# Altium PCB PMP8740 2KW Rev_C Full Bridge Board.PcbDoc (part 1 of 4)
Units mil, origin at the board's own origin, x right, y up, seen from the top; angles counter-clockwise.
Board outline 10366.14 x 5900 mil, 2 copper layers (Top Layer, Bottom Layer), stack 62 mil thick; 355 components, 213 nets, 1059 pads, 574 vias.
Unrouted connection lines stored in the file: 2.
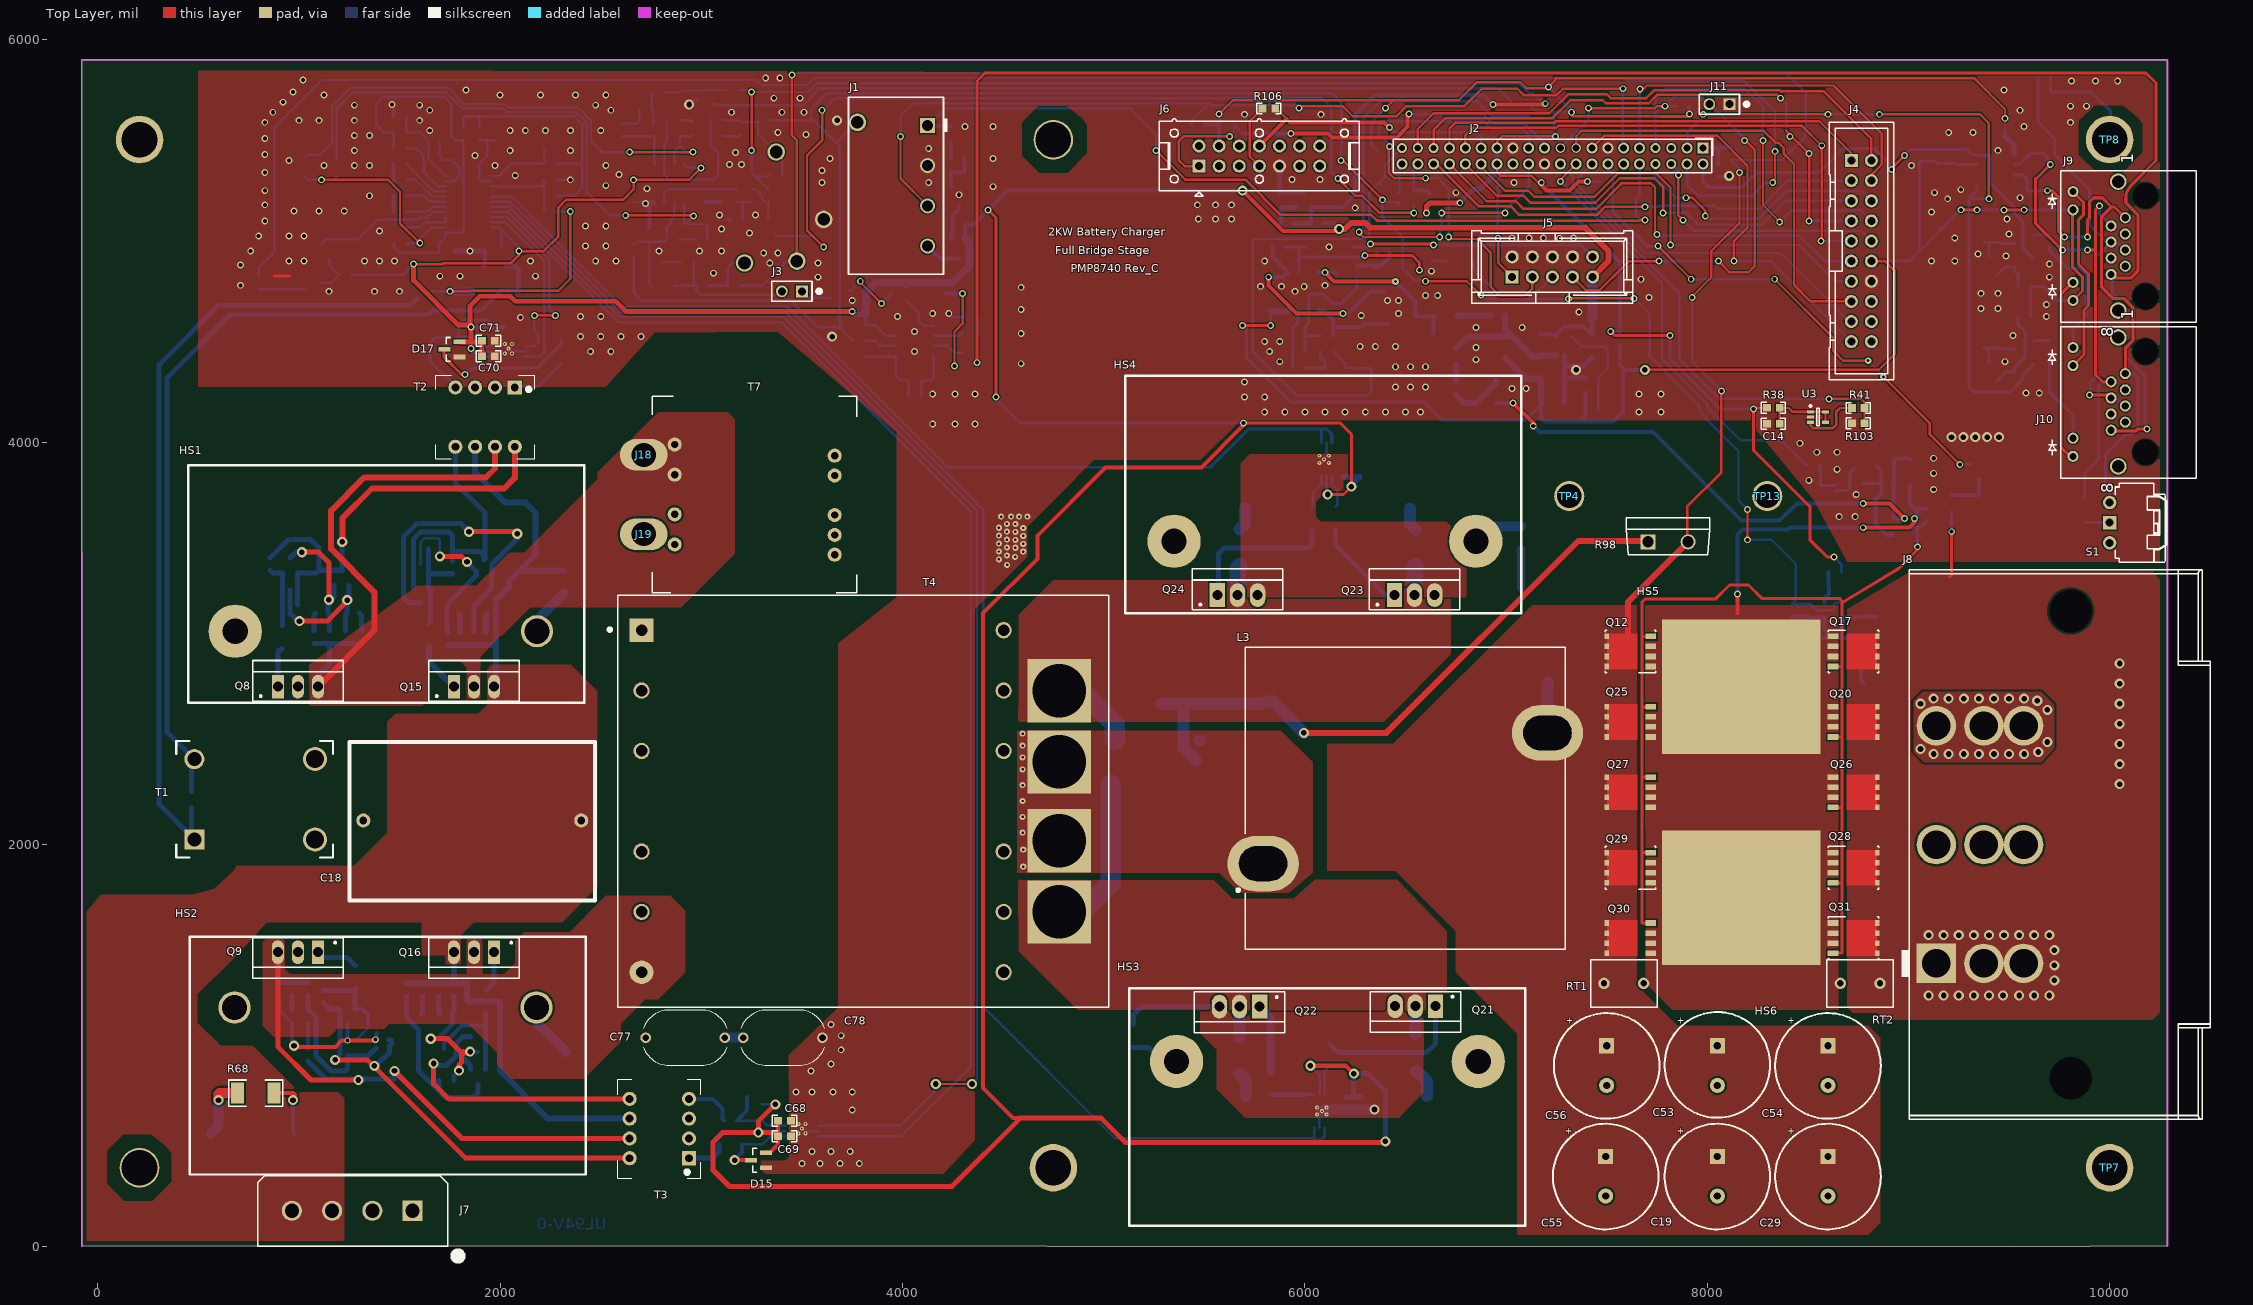
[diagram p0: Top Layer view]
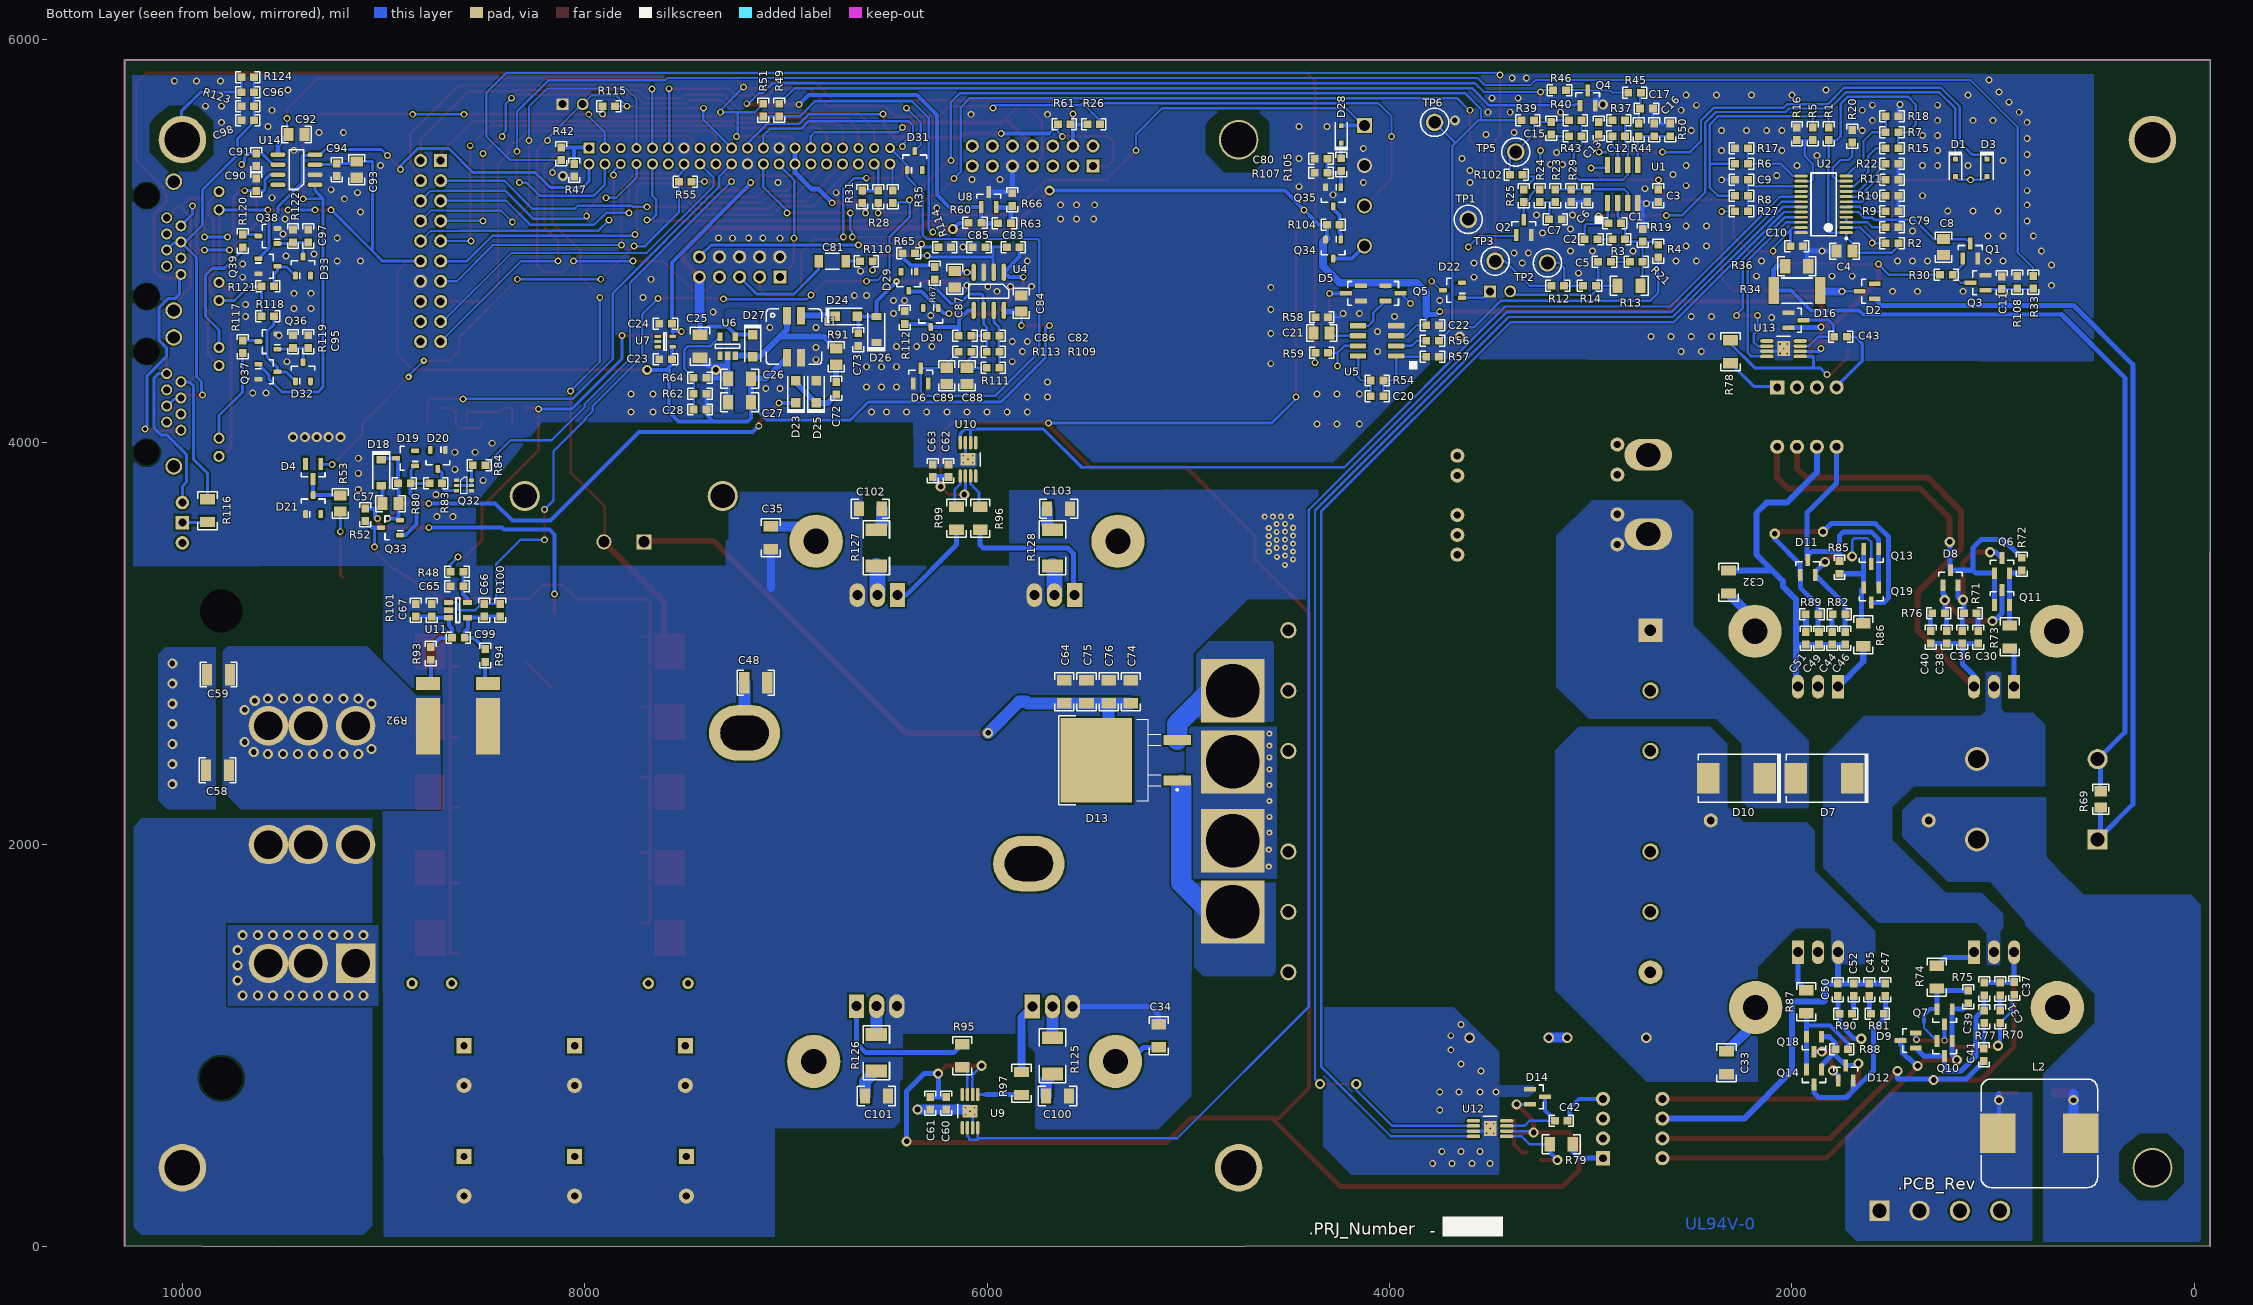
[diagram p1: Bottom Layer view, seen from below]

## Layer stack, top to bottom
Top Layer: signal copper 1.4
Dielectric: core 59.2, FR-4, Dk 4.8
Bottom Layer: signal copper 1.4

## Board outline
-78.74,5 9515,0 10287.4,5 10287.4,5900 -78.74,5900

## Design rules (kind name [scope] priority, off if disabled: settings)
AcuteAngle [All] p1: minimum=4.50000000000000E+0001 checktracksonly=FALSE
AssemblyTestPointUsage [All] p1: valid=2
Clearance [InNamedPolygon('Top Layer-gndx')] p1: gap=6
Clearance "Clearance gndx" [InNamedPolygon('Bottom Layer-gndx')] p2: gap=6
Clearance Clearance_15 [All] p3: gap=10
Clearance Clearance_18 [InNamedPolygon('Bottom Layer-No Net 17')] p4: gap=6
Clearance "Schematic Clearance Constraint_10" [InNet('NetHS2_1')] p5: gap=40
Clearance "Schematic Clearance Constraint_9" [InNet('NetHS1_2')] p6: gap=40
Clearance "Schematic Clearance Constraint_8" [InNet('NetC18_1')] p7: gap=40
Clearance "Schematic Clearance Constraint_7" [InNet('NetC30_2')] p8: gap=40
Clearance "Schematic Clearance Constraint_6" [InNet('NetC31_2')] p9: gap=40
Clearance "Schematic Clearance Constraint_5" [InNet('NetD7_1')] p10: gap=40
Clearance "Schematic Clearance Constraint_4" [InNet('NetD7_2')] p11: gap=40
Clearance "Schematic Clearance Constraint_3" [InNet('+390V')] p12: gap=40
Clearance "Schematic Clearance Constraint_2" [InNet('NetD13_1')] p13: gap=20
Clearance "Schematic Clearance Constraint_1" [InNet('NetD13_3')] p14: gap=20
Clearance "Schematic Clearance Constraint" [InNet('NetL3_1')] p15: gap=20
Clearance Clearance_14 [InNamedPolygon('Bottom Layer-No Net 9')] p16: gap=10
Clearance Clearance_13 [InNamedPolygon('Bottom Layer-No Net 9')] p17: gap=10
Clearance Clearance_12 [InNet('+390V')] p18: gap=30
Clearance Clearance_11 [InNamedPolygon('Top Layer-No Net 5')] p19: gap=30
Clearance Clearance_10 [InNamedPolygon('Top Layer-No Net 5')] p20: gap=30
Clearance Clearance_9 [InNamedPolygon('Top Layer-No Net 5')] p21: gap=20
Clearance Clearance_8 [InNamedPolygon('Top Layer-No Net 5')] p22: gap=20
Clearance Clearance_7 [InNamedPolygon('Top Layer-No Net 5')] p23: gap=20
Clearance Clearance_6 [InNamedPolygon('Bottom Layer-No Net 8')] p24: gap=10
Clearance Clearance_5 [InNamedPolygon('Top Layer-No Net 10')] p25: gap=10
Clearance Clearance_4 [InNamedPolygon('Top Layer-No Net 5')] p26: gap=10
Clearance Clearance_3 [InNamedPolygon('Bottom Layer-No Net 7')] p27: gap=10
Clearance Clearance_2 [InNamedPolygon('Bottom Layer-No Net 7')] p28: gap=10
Clearance Clearance_1 [InNamedPolygon('Top Layer-No Net 3')] p29: gap=10
Clearance Clearance_BoardEdge_MountingHoles [OnCopper and InComponentClass('Mounting Holes') vs IsKeepOut] p30: gap=40
Clearance Clearance_BoardEdge_Poly [OnCopper and InPoly vs IsKeepOut] p31: gap=40
Clearance Clearance_BoardEdge [OnCopper and Not InComponentClass('Logo') and not InComponentClass('FiducialMark') and not InRegion(1000,500,4000,800) and Not IsKeepout vs IsKeepOut] p32: gap=40
Clearance Clearance_Poly [InPolygon] p33: gap=12
ComponentClearance ComponentClearance_Logo [InComponentClass('Logo')] p1: gap=50 collisioncheckmode=3 verticalgap=100000 showdistances=FALSE
ComponentClearance ComponentClearance_ScrewToNut [(HasFootprint('NY PMS 440 0025 PH')) vs (HasFootprint('Keystone_1902C'))] p2: gap=5 collisioncheckmode=3 verticalgap=100000 showdistances=FALSE
ComponentClearance ComponentClearance_MountingHoles [InComponentClass('Mounting Holes')] p3: gap=250 collisioncheckmode=3 verticalgap=100000 showdistances=FALSE
ComponentClearance ComponentClearance_SmallPassives [HasFootprint('0201*') or HasFootprint('0402*') or HasFootprint('0508') or HasFootprint('0603*') or HasFootprint('0612') or HasFootprint('0805*') or HasFootprint('0815*') or HasFootprint('0830*') or HasFootprint('1206*') or HasFootprint('1210*') or HasFootprint('1808*') or HasFootprint('1812*') or HasFootprint('1825*') or HasFootprint('2010*') or HasFootprint('2220*') or HasFootprint('2225*') or HasFootprint('2512*') or HasFootprint('2728*') or HasFootprint('3518*') vs HasFootprint('0201*') or HasFootprint('0402*') or HasFootprint('0508') or HasFootprint('0603*') or HasFootprint('0612') or HasFootprint('0805*') or HasFootprint('0815*') or HasFootprint('0830*') or HasFootprint('1206*') or HasFootprint('1210*') or HasFootprint('1808*') or HasFootprint('1812*') or HasFootprint('1825*') or HasFootprint('2010*') or HasFootprint('2220*') or HasFootprint('2225*') or HasFootprint('2512*') or HasFootprint('2728*') or HasFootprint('3518*')] p4: gap=20 collisioncheckmode=3 verticalgap=100000 showdistances=FALSE
ComponentClearance ComponentClearance_THtoSMT [IsThruComponent vs IsSMTComponent] p5: gap=10 collisioncheckmode=3 verticalgap=100000 showdistances=FALSE
ComponentClearance ComponentClearance_THtoTH [IsThruComponent vs IsThruComponent] p6: gap=10 collisioncheckmode=3 verticalgap=100000 showdistances=FALSE
ComponentClearance [All] p7: gap=7.87 collisioncheckmode=3 verticalgap=100000 showdistances=FALSE
DiffPairsRouting [All] p1: maxlimit=100 minlimit=10 mostfreqgap=10 maxuncoupledlength=1000
FabricationTestPointUsage TestPointUsage [All] p1: valid=2 allowmultiple=FALSE
FabricationTestpoint Testpoint [All] p1: side=3 testpointundercomponent=TRUE minsize=40 maxsize=100 preferedsize=60 minholesize=0 maxholesize=40 preferedholesize=32 testpointgrid=1 allowsidetop=TRUE allowsidebottom=TRUE usegrid=TRUE gridtolerance=0.01
FanoutControl Fanout_LCC [IsLCC] p1: bgadir=Out bgaviamode=Centered fanoutstyle=Auto fanoutdirection=Alternating viagrid=1 // Fanout_LCC (Default Rule)
FanoutControl Fanout_BGA [IsBGA] p2: bgadir=Out bgaviamode=Centered fanoutstyle=Auto fanoutdirection=Alternating viagrid=1 // Fanout_BGA (Default Rule)
FanoutControl Fanout_Default [All] p4: bgadir=Out bgaviamode=Centered fanoutstyle=Auto fanoutdirection=Alternating viagrid=1 // Fanout_Default (Default Rule)
FanoutControl Fanout_Small [(CompPinCount < 5)] p5: bgadir=Out bgaviamode=Centered fanoutstyle=Auto fanoutdirection=OutThenIn viagrid=1 // Fanout_Small (Default Rule)
Height [All] p1: minheight=0 maxheight=99999 prefheight=500
HoleSize [All] p1: absolutevalues=TRUE maxlimit=251 minlimit=8 maxpercent=80.000 minpercent=20.000
MinimumAnnularRing MinimumAnnularRing_ThermalPadVias [IsVia and InAnyComponent] p1: minimumring=5.91
MinimumAnnularRing [All] p2: minimumring=9
MinimumSolderMaskSliver MinimumSolderMaskSliver_Logo [InComponentClass('Logo') vs InComponentClass('Logo')] p1: minsoldermaskwidth=0.7
MinimumSolderMaskSliver [All] p2: minsoldermaskwidth=3.94
PlaneClearance [All] p1: clearance=12
PlaneConnect [All] p1: planeconnectstyle=Relief reliefexpansion=10 reliefentries=4 reliefconductorwidth=10 reliefairgap=10
PolygonConnect [All] p1: connectstyle=Direct reliefconductorwidth=10 reliefentries=4 polygonreliefangle="90 Angle" airgapwidth=10
RoomDefinition "PMP8740 2KW Rev_C Full Bridge Control Section-B Schematic" [InComponentClass('PMP8740 2KW Rev_C Full Bridge Control Section-B Schematic')] p1: confinementstyle=ConfineIn formatcopy=TRUE lockcomponents=FALSE outline 10333,61 13993,61 13993,446 10333,446
RoomDefinition "PMP8740 2KW Rev_C Full Bridge Control Section-A Schematic" [InComponentClass('PMP8740 2KW Rev_C Full Bridge Control Section-A Schematic')] p2: confinementstyle=ConfineIn formatcopy=TRUE lockcomponents=FALSE outline -692,-1534 1308,-1534 1308,-534 -692,-534
RoomDefinition "PMP8740 2KW Rev_C Full Bridge Power Stage Schematic" [InComponentClass('PMP8740 2KW Rev_C Full Bridge Power Stage Schematic')] p3: confinementstyle=ConfineIn formatcopy=TRUE lockcomponents=FALSE outline 9558,1806 13484.25,1806 13484.25,3444.88 9558,3444.88
RoutingVias ThermalPadVias [IsVia and InAnyComponent] p1: holewidth=7.87 width=19.68 viastyle="Through Hole" minholewidth=7.87 minwidth=19.68 maxholewidth=12.99 maxwidth=23.62
RoutingVias [All] p2: holewidth=16 width=34 viastyle="Through Hole" minholewidth=7.87 minwidth=26 maxholewidth=40 maxwidth=65
SMDToCorner [All] p1: distance=30000
SilkToSilkClearance [All] p1: silktosilkclearance=5
SilkscreenOverComponentPads [All] p1: minsilkscreentomaskgap=5
SolderMaskExpansion [All] p1: expansion=1.97
Width [All] p1: maxlimit=100 minlimit=6 preferedwidth=10 checkconnectedcopper=TRUE
12 further rules are at their usual default settings.

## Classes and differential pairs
component class Header: J3 J11
component class "PMP8740 2KW Rev_C Full Bridge Control Section-B Schematic": C20 C21 C22 C80 C81 C82 C83 C84 C85 C86 C87 C88 C89 C90 C91 C92 C93 C94 C95 C96 C97 C98 D5 D6 D22 D28 D29 D30 D31 D32 D33 J1 J3 J9 J10 Q5 Q34 Q35 Q36 Q37 Q38 Q39 R26 R42 R47 R54 R56 R57 R58 R59 R65 R67 R104 R105 R107 R109 R110 R111 R112 R113 R114 R116 R117 R118 R119 R120 R121 R122 R123 R124 S1 TP8 U4 U5 U14
component class "PMP8740 2KW Rev_C Full Bridge Power Stage Schematic": C18 C19 C29 C30 C31 C32 C33 C34 C35 C36 C37 C38 C39 C40 C41 C42 C43 C44 C45 C46 C47 C48 C49 C50 C51 C52 C53 C54 C55 C56 C57 C58 C59 C60 C61 C62 C63 C64 C65 C66 C67 C68 C69 C70 C71 C74 C75 C76 C77 C78 C99 C100 C101 C102 C103 D4 D7 D8 D9 D10 D11 D12 D13 D14 D15 D16 D17 D18 D19 D20 D21 HS1 HS2 HS3 HS4 HS5 HS6 J7 J8 J18 J19 L2 L3 Q6 Q7 Q8 Q9 Q10 Q11 Q12 Q13 Q14 Q15 Q16 Q17 Q18 Q19 Q20 Q21 Q22 Q23 Q24 Q25 Q26 Q27 Q28 Q29 Q30 Q31 Q32 Q33 R48 R52 R53 R55 R68 R69 R70 R71 R72 R73 R74 R75 R76 R77 R78 R79 R80 R81 R82 R83 R84 R85 R86 R87 R88 R89 R90 R92 R93 R94 R95 R96 R97 R98 R99 R100 R101 R125 R126 R127 R128 RT1 RT2 T1 T2 T3 T4 T7 TP4 TP7 TP13 U9 U10 U11 U12 U13
component class "PMP8740 2KW Rev_C Full Bridge Control Section-A Schematic": C1 C2 C3 C4 C5 C6 C7 C8 C9 C10 C11 C12 C13 C14 C15 C16 C17 C23 C24 C25 C26 C27 C28 C72 C73 C79 D1 D2 D3 D23 D24 D25 D26 D27 J2 J4 J5 J6 J11 L1 Q1 Q2 Q3 Q4 R1 R2 R3 R4 R5 R6 R7 R8 R9 R10 R11 R12 R13 R14 R15 R16 R17 R18 R19 R20 R21 R22 R23 R24 R25 R27 R28 R29 R30 R31 R33 R34 R35 R36 R37 R38 R39 R40 R41 R43 R44 R45 R46 R49 R50 R51 R60 R61 R62 R63 R64 R66 R91 R102 R103 R106 R108 R115 TP1 TP2 TP3 TP5 TP6 U1 U2 U3 U6 U7 U8

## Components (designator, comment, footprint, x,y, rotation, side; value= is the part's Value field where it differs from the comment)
C1 "C1608C0G1H222J" 0603 2879.96,5087.8 r180 bottom
C2 "C1608X7R1H104K" 0603 2998.07,5009.06 r180 bottom
C3 "C1608X7R1E105K080AB" 0603 2663.43,5225.59 r90 bottom
C4 "C2012X7R1C225K" 0805_HV 1738.23,4950 r0 bottom
C5 "DNP" 0603 2931.14,4895.87 r180 bottom
C6 "C1608X7R1C224K" 0603 3017.76,5225.59 r270 bottom
C7 "C1608X7R1H104K" 0603 3175.24,5107.48 r180 bottom
C8 "C2012X7R1C474K" 0805_HV 1246.1,4969.69 r270 bottom
C9 "C1608C0G1H331J" 0603 2250.04,5304.33 r0 bottom
C10 "C1608X7R1E105K080AB" 0603 1975,4975 r180 bottom
C11 "C1608X7R1H104K" 0603 956.06,4792.52 r90 bottom
C12 "C1608C0G1H561J" 0603 2860.28,5520.87 r180 bottom
C13 "C1608X7R2A223K" 0603 2958.7,5560.24 r90 bottom
C14 "C1608X7R1H104K" 0603 8328.78,4091.73 r180 top
C15 "DNP" 0603 3194.92,5560.24 r270 bottom
C16 "C1608X7R1C224K" 0603 2683.11,5552.36 r90 bottom
C17 "C1608X7R1H104K" 0603 2722.48,5658.66 r180 bottom
C18 "C4AEHBU5100A11J" CAP_ECQE-1083MIL 1320,2120 r0 top
C19 "EKZM500ESS471MK20S" CAP_ZL-5X12.5MM 8050,350 r0 top
C20 "C1608C0G1H331J" 0603 4061.42,4227.96 r180 bottom
C21 "C2012X5R0J226M" 0805_HV 4337.01,4542.92 r0 bottom
C22 "C1608X7R1E105K080AB" 0603 3785.83,4582.29 r180 bottom
C23 "C1608X7R1E105K080AB" 0603 7598.19,4412.87 r0 bottom
C24 "C1608X7R1E105K080AB" 0603 7598.19,4587.87 r0 bottom
C25 "C3216X7R1E475K" 1206 7427.2,4477.56 r270 bottom
C26 "C3216X7R1A106M" 1206 7230.35,4316.14 r0 bottom
C27 "C3216X7R1A106M" 1206 7230.35,4198.03 r0 bottom
C28 "C1608C0G1H331J" 0603 7427.2,4162.6 r0 bottom
C29 "EKZM500ESS471MK20S" CAP_ZL-5X12.5MM 8600,350 r0 top
C30 "C1608X7R1H104K" 0603 1073.58,3030.87 r270 bottom
C31 "C1608X7R1H104K" 0603 965.04,1282.17 r90 bottom
C32 "CC1206KKX7RCBB102" 1206 2315,3305 r90 bottom
C33 "CC1206KKX7RCBB102" 1206 2325,915 r270 bottom
C34 "CC1206KKX7RCBB102" 1206 5147.22,1049.2 r90 bottom
C35 "CC1206KKX7RCBB102" 1206 7075,3525 r270 bottom
C36 "C1608X7R2A223K" 0603 1152.32,3030.87 r90 bottom
C37 "C1608X7R2A223K" 0603 895,1285 r270 bottom
C38 "C1608X7R2A223K" 0603 1231.06,3030.87 r90 bottom
C39 "C1608X7R2A223K" 0603 1043.78,1282.17 r270 bottom
C40 "C1608X7R1H104K" 0603 1309.8,3030.87 r270 bottom
C41 "C1608X7R1H104K" 0603 1045,955 r270 bottom
C42 "C1608X7R1E105K080AB" 0603 3145.59,627.99 r0 bottom
C43 "C1608X7R1E105K080AB" 0603 1757.7,4523.7 r0 bottom
C44 "C1608X7R1H104K" 0603 1800,3025 r270 bottom
C45 "C1608X7R1H104K" 0603 1614.21,1278.11 r90 bottom
C46 "C1608X7R2A223K" 0603 1735,3025 r90 bottom
C47 "C1608X7R2A223K" 0603 1535.47,1278.11 r270 bottom
C48 "GRM32ER71H106KA12L" 1210 7150,2805 r180 bottom
C49 "C1608X7R2A223K" 0603 1865,3025 r90 bottom
C50 "C1608X7R2A223K" 0603 1771.69,1278.11 r270 bottom
C51 "C1608X7R1H104K" 0603 1930,3025 r270 bottom
C52 "C1608X7R1H104K" 0603 1692.95,1278.11 r90 bottom
C53 "EKZM500ESS471MK20S" CAP_ZL-5X12.5MM 8050,900 r0 top
C54 "EKZM500ESS471MK20S" CAP_ZL-5X12.5MM 8600,900 r0 top
C55 "EKZM500ESS471MK20S" CAP_ZL-5X12.5MM 7495,350 r0 top
C56 "EKZM500ESS471MK20S" CAP_ZL-5X12.5MM 7500,900 r0 top
C57 "C2012X7R1E224K" 0805_HV 8965,3695 r180 bottom
C58 "GRM32ER71H106KA12L" 1210 9825,2370 r180 bottom
C59 "GRM32ER71H106KA12L" 1210 9820,2845 r180 bottom
C60 "C1608X7R1H104K" 0603 6202.91,714.37 r270 bottom
C61 "C1608X7R1E105K080AB" 0603 6281.65,714.37 r270 bottom
C62 "C1608X7R1E105K080AB" 0603 6191.77,3857.95 r90 bottom
C63 "C1608X7R1H104K" 0603 6270.51,3857.95 r90 bottom
C64 "C3216X7R2E104K" 1206 5616,2759 r90 bottom
C65 "C1608X7R1H104K" 0603 8635,3285 r0 bottom
C66 "C1608X7R2A223K" 0603 8500,3165 r270 bottom
C67 "C1608X7R2A223K" 0603 8760,3165 r270 bottom
C68 "C1608X7R1H104K" 0603 3413.31,627.99 r0 top
C69 "C1608X7R1E105K080AB" 0603 3413.31,549.25 r0 top
C70 "C1608X7R1H104K" 0603 1941.77,4426.26 r0 top
C71 "C1608X7R1E105K080AB" 0603 1941.77,4505 r0 top
C72 "C1608X7R2A223K" 0603 6750,4267.68 r90 bottom
C73 "C1608X7R1E105K080AB" 0603 6640,4510 r270 bottom
C74 "C3216X7R2E104K" 1206 5286,2759 r90 bottom
C75 "C3216X7R2E104K" 1206 5506,2759 r90 bottom
C76 "C3216X7R2E104K" 1206 5396,2759 r90 bottom
C77 "DE1E3KX222MA4BL01" CAPRD1000W60D900H1200 2920,1040 r180 top
C78 "DE1E3KX222MA4BL01" CAPRD1000W60D900H1200 3405,1040 r180 top
C79 "C0603C221J5GACTU" 0603 1502.01,5068.11 r180 bottom
C80 "C1608X7R1H103K" 0603 4340,5410 r0 bottom
C81 "C3216X5R1A107M160AC" 1206_190 6770,4900 r180 bottom
C82 "C1608X7R1H102K" 0603 5970,4530 r0 bottom
C83 "C1608C0G1H680J" 0603 5870,4970 r180 bottom
C84 "C2012X7R1C105K" 0805_HV 5830,4690 r90 bottom
C85 "C1608C0G1H272J" 0603 6040,4970 r0 bottom
C86 "C1608C0G1H680J" 0603 6110,4530 r0 bottom
C87 "C2012X7R1C105K" 0805_HV 6160,4810 r270 bottom
C88 "C2012X7R1C225K" 0805_HV 6100,4330 r270 bottom
C89 "C2012X7R1C105K" 0805_HV 6200,4330 r270 bottom
C90 "DNP" 0603 9632.5,5279.38 r90 bottom
C91 "DNP" 0603 9632.5,5404.38 r90 bottom
C92 "C2012X7R1C105K" 0805_HV 9432.5,5529.38 r180 bottom
C93 "C2012X7R1C105K" 0805_HV 9132.5,5354.38 r270 bottom
C94 "C1608X7R1H104K" 0603 9232.5,5354.38 r270 bottom
C95 "C1608X7R1H104K" 0603 9375,4500 r90 bottom
C96 "DNP" 0603 9675,5740 r0 bottom
C97 "C1608X7R1H104K" 0603 9375,5025 r90 bottom
C98 "C1608X7R1H104K" 0603 9675,5600 r0 bottom
C99 "C1608C0G1H102J" 0603 8627.97,3027.43 r180 bottom
C100 "VJ1206Y471KBEAT4X" 1206 5650,750 r180 bottom
C101 "VJ1206Y471KBEAT4X" 1206 6550,750 r180 bottom
C102 "VJ1206Y471KBEAT4X" 1206 6580,3670 r0 bottom
C103 "VJ1206Y471KBEAT4X" 1206 5645,3670 r180 bottom
D1 "BAT42WS-7-F" sod-323 1187.05,5363.39 r270 bottom
D2 "BAS21-7-F" SOT-23#1 1625,4750 r0 bottom
D3 "BAT42WS-7-F" sod-323 1029.57,5363.39 r270 bottom
D4 "BAS21-7-F" SOT-23#1 9350,3855 r270 bottom
D5 "BAT54SLT1G" SOT-23#1 4179.53,4739.77 r0 bottom
D6 "BAS21-7-F" SOT-23#1 6330,4330 r90 bottom
D7 "MURS360T3G" SMC 1840,2330 r0 bottom
D8 "BAT54SLT1G" SOT-23#1 1211.38,3326.14 r90 bottom
D9 "BAT54SLT1G" SOT-23#1 1421.73,1026.26 r0 bottom
D10 "MURS360T3G" SMC 2275,2330 r0 bottom
D11 "BAT54SLT1G" SOT-23#1 1920.59,3377.56 r90 bottom
D12 "BAT54SLT1G" SOT-23#1 1732.32,864.72 r90 bottom
D13 "VS-MURB1620CTPBF" DDPAK 5301,2419 r0 bottom
D14 "BAT54SLT1G" SOT-23#1 3263.7,746.1 r180 bottom
D15 "BAT54SLT1G" SOT-23#1 3283.39,431.14 r180 top
D16 "BAT54SLT1G" SOT-23#1 1980,4606.42 r180 bottom
D17 "BAT54SLT1G" SOT-23#1 1760,4461.42 r180 top
D18 "MMSZ5243B-7-F" SOD-123 9011.99,3847.98 r270 bottom
D19 "BAS21-7-F" SOT-23#2 8890,3920 r0 bottom
D20 "BAS21-7-F" SOT-23#2 8730,3915 r270 bottom
D21 "BAS21-7-F" SOT-23#2 9350,3690 r90 bottom
D22 "BAS21-7-F" SOT-23#2 3687.05,4755 r0 bottom
D23 "PMEG6010CEH,115" SOD-123F 6950,4250 r90 bottom
D24 "PMEG6010CEH,115" SOD-123F 6700,4625 r180 bottom
D25 "PMEG6010CEH,115" SOD-123F 6850,4250 r90 bottom
D26 "MMSZ4689T1G" SOD-123 6550,4560 r90 bottom
D27 "PMEG6010CEH,115" SOD-123F 7165,4480 r270 bottom
D28 "BAT42WS-7-F" sod-323 4240,5530 r90 bottom
D29 "BAS21-7-F" SOT-23#2 6390,4800 r270 bottom
D30 "BAS21-7-F" SOT-23#2 6280,4620 r270 bottom
D31 "BAS21-7-F" SOT-23#2 6360,5400 r90 bottom
D32 "BAS21-7-F" SOT-23#2 9400,4350 r90 bottom
D33 "BAS21-7-F" SOT-23#2 9400,4875 r90 bottom
HS1 "HEATSINK_780603B0200" HEATSINK_780603B0200#1 1433.23,3110.21 r180 top locked
HS2 "HEATSINK_780603B0200" HEATSINK_780603B0200#2 1430,1140 r0 top locked
HS3 "HEATSINK_780603B0200" HEATSINK_780603B0200#3 6111.79,872.04 r0 top
HS4 "HEATSINK_780603B0200" HEATSINK_780603B0200#3 6099.76,3557.68 r180 top
HS5 "HEATSINK_7109D" HEATSINK_7109D 8210,2785 r90 top
HS6 "HEATSINK_7109D" HEATSINK_7109D 8210,1735 r90 top
J1 "1757268" Phoenix_1757268 4125,5275 r270 top
J2 "87758-4016" MOLEX_87758-4016 7230.35,5422.44 r180 top
J3 "5-146261-1" CONN_5-146261-1 3450,4750 r180 top
J4 "66506-072LF" CONN_66506-072LF 8765.79,4950 r270 top
J5 "5103308-1" CONN_5103308-1 7230.35,4871.26 r0 top
J6 "SBH11-PBPC-D07-ST-BK" CONN_SBH11-PBPC-D07-ST-BK 5773.66,5422.44 r0 top
J7 "0015244557" CONN_0015244557 1265,180 r180 top
J8 "1762754" Phoenix_1762754 9375,2000 r90 top
J9 "2-406549-1" 2-406549-1 10100,4975 r90 top
J10 "2-406549-1" 2-406549-1 10100,4200 r90 top
J11 "5-146261-1" CONN_5-146261-1 8060,5680 r180 top
J18 "09 08 000 6124" Han-FastLock_09080006124 2713.82,3936.85 r270 top
J19 "09 08 000 6124" Han-FastLock_09080006124 2713.82,3543.15 r270 top
L1 "744878100" WE-DD_7332 6960,4525 r180 bottom
L2 "7443550230" WE-HCA2 770,565 r180 bottom
L3 "170782-a" 170782-a 6499.02,2230 r0 top
Q1 "BSS138" SOT-23#1 1113.54,4950 r90 bottom
Q2 "BSS138" SOT-23#1 3332.72,5068.11 r90 bottom
Q3 "BSS138" SOT-23#1 1074.17,4792.52 r0 bottom
Q4 "BSS138" SOT-23#1 3015,5710 r90 bottom
Q5 "MMBT2484" SOT-23#1 3982.68,4739.77 r180 bottom
Q6 "MMBT3904" SOT-23#1 955.47,3386.18 r90 bottom
Q7 "MMBT3904" SOT-23#1 1240.63,1144.37 r270 bottom
Q8 "IPP50R199CP" TO-220AB#1 995,2785 r0 top locked
Q9 "IPP50R199CP" TO-220AB#1 995,1465 r180 top locked
Q10 "MMBT3906" SOT-23#1 1240.63,986.89 r270 bottom
Q11 "MMBT3906" SOT-23#1 955.47,3228.7 r90 bottom
Q12 "CSD18532Q5B" TRANS_NexFET_Q5B#1 7610,2960 r180 top
Q13 "MMBT3904" SOT-23#1 1605.63,3431.69 r270 bottom
Q14 "MMBT3904" SOT-23#1 1889.8,845.04 r270 bottom
Q15 "IPP50R199CP" TO-220AB#1 1870,2785 r0 top locked
Q16 "IPP50R199CP" TO-220AB#1 1870,1465 r180 top locked
Q17 "CSD18532Q5B" TRANS_NexFET_Q5B#1 8735,2960 r0 top
Q18 "MMBT3906" SOT-23#1 1889.8,1007.44 r270 bottom
Q19 "MMBT3906" SOT-23#1 1605.63,3239.76 r270 bottom
Q20 "CSD18532Q5B" TRANS_NexFET_Q5B#2 8735,2610 r0 top
Q21 "IPP111N15N3G" TO-220AB#2 6548.76,1196.57 r180 top locked
Q22 "IPP111N15N3G" TO-220AB#2 5675,1194.68 r180 top locked
Q23 "IPP111N15N3G" TO-220AB#2 6545,3240 r0 top locked
Q24 "IPP111N15N3G" TO-220AB#2 5665,3240 r0 top locked
Q25 "CSD18532Q5B" TRANS_NexFET_Q5B#2 7610,2610 r180 top
Q26 "CSD18532Q5B" TRANS_NexFET_Q5B#2 8735,2260 r0 top
Q27 "CSD18532Q5B" TRANS_NexFET_Q5B#2 7610,2260 r180 top
Q28 "CSD18532Q5B" TRANS_NexFET_Q5B#1 8735,1885 r0 top
Q29 "CSD18532Q5B" TRANS_NexFET_Q5B#1 7610,1885 r180 top
Q30 "CSD18532Q5B" TRANS_NexFET_Q5B#2 7610,1535 r180 top
Q31 "CSD18532Q5B" TRANS_NexFET_Q5B#1 8735,1535 r0 top
Q32 "MMDT5551" SOT-363 8600,3785 r180 bottom
Q33 "MMBT2907A" SOT-23#2 8965,3575 r0 bottom
Q34 "IRLML5203" SOT-23#2 4280,4960 r270 bottom
Q35 "BSS138" SOT-23#2 4280,5220 r270 bottom
Q36 "BSS138" SOT-23#2 9575,4500 r0 bottom
Q37 "BSS138" SOT-23#2 9575,4350 r180 bottom
Q38 "BSS138" SOT-23#2 9575,5025 r0 bottom
Q39 "BSS138" SOT-23#2 9575,4875 r180 bottom
R1 "CRCW06031R00FKEA" 0603 1816.97,5532.68 r270 bottom
R2 "CRCW060310K0FKEA" 0603 1502.01,4989.37 r180 bottom
R3 "CRCW060368K1FKEA" 0603 2860.28,5009.06 r0 bottom
R4 "CRCW0603100KFKEA" 0603 2663.43,4950 r90 bottom
R5 "CRCW06038K25FKEA" 0603 1895.71,5532.68 r90 bottom
R6 "CRCW06038K25FKEA" 0603 2250.04,5383.07 r0 bottom
R7 "CRCW060315K4FKEA" 0603 1502.01,5540.55 r180 bottom
R8 "Do Not Populate" 0603 2250.04,5225.59 r0 bottom
R9 "CRCW060349K9FKEA" 0603 1502.01,5146.85 r0 bottom
R10 "CRCW060349K9FKEA" 0603 1502.01,5225.59 r0 bottom
R11 "CRCW060349K9FKEA" 0603 1502.01,5304.33 r0 bottom
R12 "CRCW060349R9FKEA" 0603 3163.43,4777.76 r180 bottom
R13 "CRCW120633K2FKEA" 1206 2809.09,4777.76 r0 bottom
R14 "CRCW06032K49FKEA" 0603 3005.94,4777.76 r180 bottom
R15 "CRCW060360K4FKEA" 0603 1502.01,5461.81 r180 bottom
R16 "CRCW06034K64FKEA" 0603 1974.45,5532.68 r270 bottom
R17 "CRCW0603348RFKEA" 0603 2250.04,5461.81 r180 bottom
R18 "CRCW0603562RFKEA" 0603 1502.01,5619.29 r0 bottom
R19 "CRCW06032K37FKEA" 0603 2742.17,5028.74 r270 bottom
R20 "CRCW060390K9FKEA" 0603 1698.86,5520.87 r270 bottom
R21 "DNP" 0603 2773.66,4895.87 r0 bottom
R22 "CRCW060313K0FKEA" 0603 1502.01,5383.07 r0 bottom
R23 "CRCW060347K5FKEA" 0603 3175.24,5225.59 r270 bottom
R24 "CRCW0603100KFKEA" 0603 3253.98,5225.59 r90 bottom
R25 "CRCW06034K75FKEA" 0603 3332.72,5225.59 r270 bottom
R26 "CRCW06034K75FKEA" 0603 5470,5580 r0 bottom
R27 "CRCW06031K00FKEA" 0603 2250.04,5146.85 r0 bottom
R28 "CRCW06031K00FKEA" 0603 6540,5220 r270 bottom
R29 "CRCW0603102KFKEA" 0603 3096.5,5225.59 r90 bottom
R30 "CRCW0603100KFKEA" 0603 1231.65,4831.89 r180 bottom
R31 "CRCW060310K0FKEA" 0603 6620,5220 r270 bottom
R33 "CRCW060310K0FKEA" 0603 800,4795 r90 bottom
R34 "CRCW251216R2FKEG" 2512 1974.45,4753.15 r180 bottom
R35 "CRCW06034K75FKEA" 0603 6470,5220 r270 bottom
R36 "0 Ohm" 1206 1975,4875 r180 bottom
R37 "CRCW0603150KFKEA" 0603 2860.28,5599.61 r0 bottom
R38 "CRCW060333R2FKEA" 0603 8328.78,4170.47 r180 top
R39 "CRCW060349R9FKEA" 0603 3313.03,5599.61 r180 bottom
R40 "CRCW060328K0FKEA" 0603 3076.81,5599.61 r180 bottom
R41 "CRCW060347K5FKEA" 0603 8750,4170 r0 top
R42 "CRCW060360K4FKEA" 0603 8116.18,5434.25 r270 bottom
R43 "DNP" 0603 3076.81,5520.87 r0 bottom
R44 "CRCW060347K5FKEA" 0603 2761.85,5552.36 r90 bottom
R45 "CRCW0603100KFKEA" 0603 2781.54,5737.4 r0 bottom
R46 "CRCW06034K75FKEA" 0603 3155,5750 r180 bottom
R47 "CRCW06034K75FKEA" 0603 8053.19,5351.57 r270 bottom
R48 "CRCW0603100RFKEA" 0603 8635,3355 r0 bottom
R49 "CRCW06031K00FKEA" 0603 7033.5,5650.79 r90 bottom
R50 "CRCW0603102KFKEA" 0603 2604.37,5552.36 r270 bottom
R51 "CRCW060310K0FKEA" 0603 7112.24,5650.79 r90 bottom
R52 "CRCW0603100KFKEA" 0603 9090,3640 r90 bottom
R53 "CRCW080510K0FKEA" 0805_HV 9215,3695 r270 bottom
R54 "CRCW060330K1FKEA" 0603 4061.42,4306.7 r0 bottom
R55 "CRCW060310K0FKEA" 0603 7500,5295 r0 bottom
R56 "CRCW060310K0FKEA" 0603 3785.83,4503.55 r180 bottom
R57 "CRCW060310K0FKEA" 0603 3785.83,4424.81 r0 bottom
R58 "CRCW06031K00FKEA" 0603 4337.01,4621.66 r0 bottom
R59 "CRCW06031K00FKEA" 0603 4337.01,4444.49 r180 bottom
R60 "CRCW06031K00FKEA" 0603 6060,5090 r0 bottom
R61 "CRCW060347K5FKEA" 0603 5616.18,5579.92 r0 bottom
R62 "CRCW0603105KFKEA" 0603 7427.2,4241.34 r180 bottom
R63 "CRCW060310K0FKEA" 0603 5913.43,5087.8 r0 bottom
R64 "CRCW060320K0FKEA" 0603 7427.2,4320.08 r0 bottom
R65 "CRCW060322K1FKEA" 0603 6390,4940 r0 bottom
R66 "CRCW060310K0FKEA" 0603 5874.06,5205.91 r270 bottom
R67 "CRCW060322K1FKEA" 0603 6260,4840 r270 bottom
R68 "CRCW201010R0FKEF" 2010 785,765 r180 top
R69 "CRCW0805100KJNEA" 0805_HV 465.04,2225 r270 bottom
R70 "CRCW0603100RFKEA" 0603 965.04,1144.37 r270 bottom
R71 "CRCW0603100RFKEA" 0603 1112.95,3149.96 r0 bottom
R72 "CRCW0603100RFKEA" 0603 857.05,3394.06 r270 bottom
R73 "CRCW120610R0FKEA" 1206 916.1,3031.85 r270 bottom
R74 "CRCW120610R0FKEA" 1206 1280,1341.22 r90 bottom
R75 "CRCW0603100RFKEA" 0603 1122.52,1242.8 r90 bottom
R76 "CRCW0603100RFKEA" 0603 1270.43,3149.96 r180 bottom
R77 "CRCW0603100RFKEA" 0603 1043.78,1144.37 r90 bottom
R78 "CRCW12062R21FKEA" 1206 2305,4450 r270 bottom
R79 "CRCW12062R21FKEA" 1206 3145.59,509.88 r180 bottom
R80 "CRCW060310K0FKEA" 0603 8896.38,3796.1 r0 bottom
R81 "CRCW0603100RFKEA" 0603 1574.84,1160 r180 bottom
R82 "CRCW0603100RFKEA" 0603 1765,3145 r180 bottom
R83 "CRCW06031K00FKEA" 0603 8740,3795 r0 bottom
R84 "CRCW06031K00FKEA" 0603 8525,3885 r0 bottom
R85 "CRCW0603100RFKEA" 0603 1763.11,3377.56 r270 bottom
R86 "CRCW120610R0FKEA" 1206 1645,3042.91 r270 bottom
R87 "CRCW120610R0FKEA" 1206 1929.17,1219.06 r90 bottom
R88 "CRCW0603100RFKEA" 0603 1752.01,982.83 r180 bottom
R89 "CRCW0603100RFKEA" 0603 1900,3145 r180 bottom
R90 "CRCW0603100RFKEA" 0603 1732.32,1160 r0 bottom
R91 "CRCW080547R5FKEA" 0805_HV 6750,4425 r90 bottom
R92 "BVR-Z-R0002-1.0" CSM-3637 8630,2640 r180 bottom
R93 "CRCW06031K00FKEA" 0603 8765,2950 r270 bottom
R94 "CRCW06031K00FKEA" 0603 8495,2940 r270 bottom
R95 "CRCW12062R21FKEA" 1206 6124.17,950.59 r90 bottom
R96 "CRCW12062R21FKEA" 1206 6034.29,3621.73 r270 bottom
R97 "CRCW12062R21FKEA" 1206 5828.9,812.8 r270 bottom
R98 "RTO020F10000JTE3" TO-220-2 7805,3505 r0 top
R99 "CRCW12062R21FKEA" 1206 6152.4,3621.73 r90 bottom
R100 "CRCW0603165KFKEA" 0603 8420,3165 r270 bottom
R101 "CRCW0603165KFKEA" 0603 8840,3165 r270 bottom
R102 "CRCW060327K4FKEA" 0603 3370,5330 r180 bottom
R103 "CRCW0603169KFKEA" 0603 8750,4095 r0 top
R104 "CRCW0603100KFKEA" 0603 4280,5080 r180 bottom
R105 "CRCW06034K75FKEA" 0603 4240,5380 r90 bottom
R106 "RC0603FR-07332RL" 0603 5820.91,5658.66 r180 top
R107 "CRCW06031M00FKEA" 0603 4340,5340 r180 bottom
R108 "CRCW0603100KFKEA" 0603 880,4795 r270 bottom
R109 "CRCW060322K1FKEA" 0603 5970,4450 r180 bottom
R110 "CRCW060333R2FKEA" 0603 6600,4900 r0 bottom
R111 "CRCW060310K0FKEA" 0603 5970,4370 r0 bottom
R112 "CRCW060322K1FKEA" 0603 6410,4620 r270 bottom
R113 "CRCW060322K1FKEA" 0603 6110,4450 r180 bottom
R114 "CRCW06031R00FKEA" 0603 6210,4970 r180 bottom
R115 "CRCW060310K0FKEA" 0603 7880,5670 r0 bottom
R116 "CRCW1206121RFKEA" 1206 9875,3660 r270 bottom
R117 "CRCW0603100RFKEA" 0603 9700,4475 r270 bottom
R118 "CRCW06034K75FKEA" 0603 9575,4625 r180 bottom
R119 "CRCW06031M00FKEA" 0603 9450,4500 r270 bottom
R120 "CRCW0603100RFKEA" 0603 9700,5000 r270 bottom
R121 "CRCW06034K75FKEA" 0603 9575,4775 r180 bottom
R122 "CRCW06031M00FKEA" 0603 9450,5025 r270 bottom
R123 "CRCW06031K00FKEA" 0603 9675,5670 r180 bottom
R124 "DNP" 0603 9675,5815 r180 bottom
R125 "CRCW201010R0FKEF" 2010 5675,950 r90 bottom
R126 "CRCW201010R0FKEF" 2010 6550,965.41 r90 bottom
R127 "CRCW201010R0FKEF" 2010 6550,3475 r270 bottom
R128 "CRCW201010R0FKEF" 2010 5675,3475 r270 bottom
RT1 "PTCCL09H171HBE" S153 7585,1310 r0 top
RT2 "PTCCL09H171HBE" S153 8760,1310 r0 top
S1 "NK236W" SW_NK236W 10000,3600 r90 top
T1 "CS4100V-01L" XFMR_CS4200V-01L 780,2225 r90 top
T2 "AF4779" XFMR_VITEC-492x472x452 1925,4125 r270 top
T3 "AF4779" XFMR_VITEC-492x472x452 2791.26,588.62 r180 top
T4 "PQ50-50 145400-A" "Kaschke_PQ50-50 145400-A" 3805,2215 r0 top
T7 "PQ20-149" XFMR_PQ20-149 3265,3740 r0 top
TP1 "5006" Keystone5006 3608.31,5107.48 r180 bottom
TP2 "5008" Keystone5008 3214.61,4890.94 r180 bottom
TP3 "5005" Keystone5005 3475,4900 r180 bottom
TP4 "Suggest using a net name here" CONN_8600-0-05-80-00-00-03-0#1 7313.82,3732.32 r0 top
TP5 "5008" Keystone5008 3372.09,5442.13 r0 bottom
TP6 "5005" Keystone5005 3775.63,5589.76 r0 bottom
TP7 "Suggest using a net name here" CONN_8600-0-05-80-00-00-03-0#2 10000,393.7 r0 top
TP8 "Suggest using a net name here" CONN_8600-0-05-80-00-00-03-0#3 10000,5615 r0 top
TP13 "Suggest using a net name here" CONN_8600-0-05-80-00-00-03-0#1 8298.07,3732.32 r90 top
U1 "TLC272CD" SO8 2840.59,5284.65 r90 bottom
U2 "UCC28950PW" PW0024A_N 1841.89,5182.49 r0 bottom
U3 "LM94022QBIMG" MAA05A_N 8550,4125 r0 top
U4 "TLC2272ACDA" D0008A_N 5991.79,4750 r270 bottom
U5 "UCC29002D" SO8 4061.42,4503.55 r0 bottom
U6 "TPS560200DBV" DBV0005A_N 7289.41,4477.56 r90 bottom
U7 "TPS715345DCKR" DCK0005A_N 7600,4500.31 r180 bottom
U8 "TL431AIDBZ" DBZ0003A_N 5992.17,5205.91 r90 bottom
U9 "UCC27524DGN" DGN0008D_N 6084.8,675 r90 bottom
U10 "UCC27524DGN" DGN0008D_N 6095,3915 r270 bottom
U11 "OPA378AIDBV" DBV0005A_N 8630,3165 r180 bottom
U12 "UCC27524DGN" DGN0008D_N 3499.92,588.62 r180 bottom
U13 "UCC27524DGN" DGN0008D_N 2041.18,4464.65 r180 bottom
U14 "SN65HVD256D" D0008A_L 9432.5,5354.38 r0 bottom

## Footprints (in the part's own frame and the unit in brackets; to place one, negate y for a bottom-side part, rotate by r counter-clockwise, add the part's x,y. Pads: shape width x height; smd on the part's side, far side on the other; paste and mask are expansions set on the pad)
2-406549-1 [mm] "Connector; PCB Jack, Thru-Hole; 1-Port, 8 Positions, 8 Loaded; Shielded with LEDs; Right Angle"
  round 1.4 hole 0.89: 1(3.57,0.57) 2(2.55,2.35) 3(1.53,0.57) 4(0.51,2.35) 5(-0.51,0.57) 6(-1.53,2.35) 7(-2.55,0.57) 8(-3.57,2.35) 9(6.87,7.17) 10(4.58,7.17) 11(-4.58,7.17) 12(-6.87,7.17)
  round 2.1 hole 1.57 unplated: MH1(8.14,1.46) MH4(-8.14,1.46)
  round 2.95 hole 3.25 unplated: MH2(6.36,-1.97) MH3(-6.36,-1.97)
  silkscreen extent -9.6,-8.4 9.5,10.26, body extent -9.33,-8.22 9.3,8.5, height 14.66
0603 [mm] "0603 from SM-752 data"
  rect 1x0.95 smd: 1(-0.8,0) 2(0.8,0)
  silkscreen extent -1.52,-0.69 1.52,0.69, body extent -0.87,-0.47 0.87,0.47, height 0.85
0805_HV [mil] "0805 with 30mil clearance between pads"
  rect 50x63 smd: 1(-40,0) 2(40,0)
  silkscreen extent -74,-40 74,40, body extent -43,-29 43,29, height 43
1206 [mm] "1206 from SM-752 data"
  rect 1.3x1.85 smd: 1(-1.45,0) 2(1.45,0)
  silkscreen extent -2.4,-1.21 2.4,1.21, body extent -1.7,-0.9 1.7,0.9, height 1.35
1206_190 [mm] "1206_190"
  rect 1.1x1.6 smd: 1(-1.7,0) 2(1.7,0)
  silkscreen extent -0.9,-1 0.9,1, body extent -1.75,-0.95 1.75,0.95, height 1.9
1210 [mm] "1210 from SM-752 data"
  rect 1.3x2.7 smd: 1(-1.45,0) 2(1.45,0)
  silkscreen extent -2.32,-1.57 2.32,1.57, body extent -1.7,-1.35 1.7,1.35, height 1.35
2010 [mm] "Chip Capacitor, Body 5.08x2.54mm, IPC Medium Density"
  rect 1.6x2.7 smd: 1(-2.3,0) 2(2.3,0)
  silkscreen extent -3.42,-1.65 3.42,1.65, body extent -2.73,-1.45 2.73,1.45, height 1.66
2512 [mm] "Chip Resistor, Body 6.3x3.2mm, IPC Medium Density"
  rect 1.3x3.4 smd: 1(-2.95,0) 2(2.95,0)
  silkscreen extent -1.9,-1.6 1.9,1.6, body extent -3.22,-1.67 3.22,1.67, height 0.71
170782-a [mm] "Kaschke"
  oval 9x7 hole 4.4 slot 6.1 at 0 deg: 1(-17.95,-8.25) 2(17.95,8.25)
  silkscreen extent -21.2,-19.05 20.2,19.05, body extent -20.2,-19.05 20.2,19.05, height 36.1
CAP_ECQE-1083MIL [mil]
  round 70 hole 38: 1(0,0) 2(1083,0)
CAP_ZL-5X12.5MM [mil]
  rect 75x75 hole 36: 1(0,100)
  round 75 hole 36: 2(0,-97)
CAPRD1000W60D900H1200 [mm] "Disk, Radial Capacitor"
  round 1.35 hole 0.85: 1(-5,0) 2(5,0)
  silkscreen extent -5.3,-3.5 5.3,3.5, body extent -4.48,-3.5 4.48,3.5, height 11.99
CONN_5-146261-1 [mm] "Sullins"
  rect 1.5x1.5 hole 1.02: 1(-1.27,0)
  round 1.5 hole 1.02: 2(1.27,0)
  silkscreen extent -3.68,-1.27 2.54,1.27, body extent -2.51,-1.27 2.51,1.27, height 10.87
CONN_8600-0-05-80-00-00-03-0#1 [mil] "Mill-Max"
  round 150 hole 120: 1(0,0)
  body extent -36,-36 36,36, height 400
CONN_8600-0-05-80-00-00-03-0#2 [mil] "Mill-Max"
  round 236.22 hole 177.17: 1(0,0)
  body extent -36,-36 36,36, height 400
CONN_8600-0-05-80-00-00-03-0#3 [mil] "Mill-Max"
  round 236.22 hole 177.17: 1(0,-111.06)
  body extent -36,-36 36,36, height 400
CONN_66506-072LF [mm] "FCI"
  rect 1.65x1.65 hole 1.016: 1(-11.43,-1.27)
  round 1.65 hole 1.016: 2(-11.43,1.27) 3(-8.89,-1.27) 4(-8.89,1.27) 5(-6.35,-1.27) 6(-6.35,1.27) 7(-3.81,-1.27) 8(-3.81,1.27) 9(-1.27,-1.27) 10(-1.27,1.27) 11(1.27,-1.27) 12(1.27,1.27) 13(3.81,-1.27) 14(3.81,1.27) 15(6.35,-1.27) 16(6.35,1.27) 17(8.89,-1.27) 18(8.89,1.27) 19(11.43,-1.27) 20(11.43,1.27)
  silkscreen extent -16.26,-4.06 16.26,4.06, body extent -16.26,-4.06 16.26,4.06, height 9.29
CONN_5103308-1 [mm] "TE Connectivity (AMP) Rev E datasheet"
  rect 1.65x1.65 hole 1.016 mask+0: 1(-5.08,-1.27)
  round 1.65 hole 1.016 mask+0: 2(-5.08,1.27) 3(-2.54,-1.27) 4(-2.54,1.27) 5(0,-1.27) 6(0,1.27) 7(2.54,-1.27) 8(2.54,1.27) 9(5.08,-1.27) 10(5.08,1.27)
  silkscreen extent -10.16,-4.57 10.16,4.57, body extent -10.16,-4.57 10.16,4.57, height 9.87
CONN_0015244557 [mil] "Molex"
  rect 100x100 hole 70: 1(-300,0)
  round 100 hole 70: 2(-100,0) 3(100,0) 4(300,0)
  silkscreen extent -543,-175 470,243, body extent -461,-163 461,163, height 404
CONN_SBH11-PBPC-D07-ST-BK [mm] "Sullins recommended land pattern"
  rect 1.65x1.65 hole 1.016 mask+0: 1(-7.62,-1.27)
  round 1.65 hole 1.016 mask+0: 2(-7.62,1.27) 3(-5.08,-1.27) 4(-5.08,1.27) 5(-2.54,-1.27) 6(-2.54,1.27) 7(0,-1.27) 8(0,1.27) 9(2.54,-1.27) 10(2.54,1.27) 11(5.08,-1.27) 12(5.08,1.27) 13(7.62,-1.27) 14(7.62,1.27)
  silkscreen extent -12.64,-5.08 12.64,4.7, body extent -12.64,-4.4 12.64,4.7, height 9.12
CSM-3637 [mil]
  rect 120x66 smd: 1(-148.5,160.6) 3(148.5,160.6)
  rect 120x280 smd: 2(-148.5,-52.5) 4(148.5,-52.5)
D0008A_L [mm] "SOIC, 8-Leads, Body 4.9x3.9mm, Pitch 1.27mm, IPC High Density"
  oval 1.9x0.6 smd: 1(-2.35,1.905) 2(-2.35,0.635) 3(-2.35,-0.635) 4(-2.35,-1.905) 5(2.35,-1.905) 6(2.35,-0.635) 7(2.35,0.635) 8(2.35,1.905)
  silkscreen extent -0.9,-2.5 0.9,2.5, body extent -3,-2.45 3,2.45, height 1.63
D0008A_N [mm] "SOIC, 8-Leads, Body 4.9x3.9mm, Pitch 1.27mm, IPC Medium Density"
  oval 2.2x0.6 smd: 1(-2.4,1.905) 2(-2.4,0.635) 3(-2.4,-0.635) 4(-2.4,-1.905) 5(2.4,-1.905) 6(2.4,-0.635) 7(2.4,0.635) 8(2.4,1.905)
  silkscreen extent -0.9,-2.5 0.9,2.5, body extent -3,-2.45 3,2.45, height 1.63
DBV0005A_N [mm] "SOT23, 5-Leads, Body 2.9x1.6mm, Pitch 0.95mm, Lead Span 2.8mm, IPC Medium Density"
  rect 1.1x0.65 smd: 1(-1.2,0.95) 2(-1.2,0) 3(-1.2,-0.95) 4(1.2,-0.95) 5(1.2,0.95)
  silkscreen extent -0.25,-1.55 0.25,1.55, body extent -1.42,-1.46 1.42,1.46, height 1.08
DBZ0003A_N [mm] "SOT23, 3-Leads, Body 2.9x1.3mm, Pitch 0.95mm, Lead Span 2.4mm, IPC Medium Density"
  rect 1.5x0.6 smd: 1(-0.95,0.95) 2(-0.95,-0.95) 3(0.95,0)
  silkscreen extent 0.2,-1.5 0.7,1.5, body extent -1.26,-1.46 1.26,1.46, height 0.96
DCK0005A_N [mm] "SOT353, 5-Leads, Body 2x1.3mm, Pitch 0.65mm, Lead Span 2.1mm, IPC Medium Density"
  rect 0.85x0.4 smd: 1(-0.95,0.65) 2(-0.95,0) 3(-0.95,-0.65) 4(0.95,-0.65) 5(0.95,0.65)
  silkscreen extent -0.15,-1.1 0.15,1.1, body extent -1.14,-1 1.14,1, height 0.94
DDPAK [mil] "D2-PAK, 3-Pads, Body 9.7x10.4mm (max), TO-263AB, using Vishay Silionix recommended pad sizes"
  rect 135x49.49 smd: 1(-246.06,100) 3(-246.06,-100)
  rect 355x420 smd paste-181.1: 4(155.51,0)
  silkscreen extent -251,-220 344,220, body extent -295,-202 324,202, height 180
DGN0008D_N [mm] "TSOP, 8-Leads, Body 3x3mm, Pitch 0.65mm, Thermal Pad 1.89x1.57mm, IPC Medium Density"
  oval 1.7x0.45 smd: 1(-2.1,0.975) 2(-2.1,0.325) 3(-2.1,-0.325) 4(-2.1,-0.975) 5(2.1,-0.975) 6(2.1,-0.325) 7(2.1,0.325) 8(2.1,0.975)
  rect 1.57x1.89 smd: 9(0,0)
  silkscreen extent -0.85,1.55 0.85,1.55, body extent -2.45,-1.5 2.45,1.5, height 0.94
Han-FastLock_09080006124 [mm] "Harting"
  oval 4x6 hole 3.048: 1(0,0)
  body extent -4.3,-4.3 4.3,4.3, height 16.6
HEATSINK_7109D [mm]
  rect 17x20 smd: 1(0,1.035)
HEATSINK_780603B0200#1 [mil]
  round 160 / inner round 265 / far side round 265 hole 125: 1(-750,50)
  round 265 hole 125: 2(750,50)
HEATSINK_780603B0200#2 [mil]
  round 160 / inner round 265 / far side round 265 hole 125: 1(-750,50) 2(750,50)
HEATSINK_780603B0200#3 [mil]
  round 265 hole 125: 1(-750,50) 2(750,50)
"Kaschke_PQ50-50 145400-A" [mm] "Kaschke"
  rect 3x3 hole 1.45: 1(-28,21.6)
  round 2.05 hole 1.45: 2(-28,13.98) 3(-28,6.36) 4(-28,-6.34) 5(-28,-13.96) 7(17.72,-21.58) 8(17.72,-13.96) 9(17.72,-6.34) 10(17.72,6.36) 11(17.72,13.98) 12(17.72,21.6)
  round 3 hole 1.45: 6(-28,-21.58)
  rect 8x8 hole 6.75: 13(24.72,-13.97) 14(24.72,-4.97) 15(24.72,4.97) 16(24.72,13.97)
  silkscreen extent -32.15,-26 31,26, body extent -31,-26 31,26, height 53
Keystone5005 [mil] "Keystone Compact loops"
  round 87 hole 63: 1(0,0)
  silkscreen extent -70,-70 70,70, body extent -63,-63 62,63, height 225
Keystone5006 [mil] "Keystone Compact loops"
  round 87 hole 63: 1(0,0)
  silkscreen extent -70,-70 70,70, body extent -63,-63 62,63, height 225
Keystone5008 [mil] "Keystone Compact loops"
  round 87 hole 63: 1(0,0)
  silkscreen extent -70,-70 70,70, body extent -63,-63 62,63, height 225
MAA05A_N [mm] "SOT353, 5-Leads, Body 2x1.3mm, Pitch 0.65mm, Lead Span 2.1mm, IPC Medium Density"
  rect 0.85x0.4 smd: 1(-0.95,0.65) 2(-0.95,0) 3(-0.95,-0.65) 4(0.95,-0.65) 5(0.95,0.65)
  silkscreen extent -1.07,-1.1 0.15,1.52, body extent -0.7,-1.1 0.7,1.1, height 1.1
MOLEX_87758-4016 [mm] "MOLEX"
  rect 1.4x1.4 hole 0.889: 1(-19,-1)
  round 1.4 hole 0.889: 2(-19,1) 3(-17,-1) 4(-17,1) 9(-11,-1) 10(-11,1) 11(-9,-1) 12(-9,1) 13(-7,-1) 14(-7,1) 15(-5,-1) 16(-5,1) 18(-3,1) 20(-1,1) 21(1,-1) 22(1,1) 23(3,-1) 24(3,1) 25(5,-1) 26(5,1) 27(7,-1) 28(7,1) 29(9,-1) 30(9,1) 31(11,-1) 32(11,1) 33(13,-1) 34(13,1) 36(15,1) 38(17,1) 40(19,1)
  round 1.27 hole 0.787: 5(-15,-1) 6(-15,1) 7(-13,-1) 8(-13,1) 35(15,-1) 37(17,-1) 39(19,-1)
  round 1.2 / inner round 1.4 / far side round 1.4 hole 0.889: 17(-3,-1) 19(-1,-1)
  silkscreen extent -20.31,-2.31 20.1,2.1, body extent -20.05,-2.1 20.05,2.1, height 5.75
Phoenix_1757268 [mm] "Header (shrouded), 5.08mm, 4x1, R/A, TH"
  rect 1.9x1.9 hole 1.4: 1(-7.62,0)
  round 1.9 hole 1.4: 2(-2.54,0) 3(2.54,0) 4(7.62,0)
  silkscreen extent -11.16,-10 11.16,2.5, body extent -11.16,-10 11.16,2, height 8.6
Phoenix_1762754 [mm] "Header (shrouded), 15mm, 3x1, R/A, TH"
  round 5 hole 3.6: 1(-15,-5) 1(-15,0) 2(0,6) 2(0,0) 2(0,-5) 3(15,-5) 3(15,0) 3(15,6)
  rect 5x5 hole 3.6: 1(-15,6)
  round 0 hole 5.4 unplated: MH1(-29.5,-10.95) MH2(29.5,-10.95)
  silkscreen extent -34.7,-28.55 34.7,10.4, body extent -34.7,-28.55 34.7,9.45, height 28.5
PW0024A_N [mm] "TSOP, 24-Leads, Body 7.8x4.4mm, Pitch 0.65mm, IPC Medium Density"
  oval 1.7x0.35 smd: 1(-2.85,3.575) 2(-2.85,2.925) 3(-2.85,2.275) 4(-2.85,1.625) 5(-2.85,0.975) 6(-2.85,0.325) 7(-2.85,-0.325) 8(-2.85,-0.975) 9(-2.85,-1.625) 10(-2.85,-2.275) 11(-2.85,-2.925) 12(-2.85,-3.575) 13(2.85,-3.575) 14(2.85,-2.925) 15(2.85,-2.275) 16(2.85,-1.625) 17(2.85,-0.975) 18(2.85,-0.325) 19(2.85,0.325) 20(2.85,0.975) 21(2.85,1.625) 22(2.85,2.275) 23(2.85,2.925) 24(2.85,3.575)
  silkscreen extent -2.97,-3.95 1.6,4.42, body extent -2.25,-3.95 2.25,3.95, height 1.2
S153 [mm] "EPCOS"
  round 1.45 hole 0.8: 1(-2.5,0) 2(2.5,0)
  silkscreen extent -4.2,-3 4.2,3, body extent -4.23,-3 4.23,3, height 12.99
SMC [mil] "Molded Diode, 2-Leads, Body 6.9x5.8mm, IPC Medium Density, based on OnSemi component dimensions and land patterns"
  rect 110x150 smd: 1(-140.49,0) 2(140.49,0)
  silkscreen extent -221,-124 189,123, body extent -156,-116 156,116, height 91
SO8 [mil]
  rect 80x26 smd: 1(-95,75) 2(-95,25) 3(-95,-25) 4(-95,-75) 5(94,-75) 6(94,-25) 7(94,25) 8(94,75)
  silkscreen extent -200,100 -160,140
SOD-123 [mm] "On Semi recommended land pattern"
  rect 0.915x1.22 smd: 1(-1.637,0) 2(1.637,0)
  silkscreen extent -2.74,-1.17 2.03,1.17, body extent -1.93,-0.9 1.93,0.9, height 1.35
SOD-123F [mm] "NXP recommended land pattern"
  rect 1.2x1.2 smd paste-0.05: 1(-1.4,0) 2(1.4,0)
  silkscreen extent -2.64,-1.12 2.01,1.12, body extent -1.8,-0.85 1.8,0.85, height 1.2
sod-323 [mm] "NXP recommended land pattern"
  rect 0.6x0.6 smd paste-0.05: 1(-1.1,0) 2(1.1,0)
  silkscreen extent -2.06,-0.86 1.53,0.86, body extent -1.3,-0.67 1.3,0.68, height 1.1
SOT-23#1 [mm] "SOT23, 3-Leads, Body 2.9x1.3mm, Pitch 0.95mm, Lead Span 2.5mm, IPC Medium Density"
  rect 1.5x0.6 smd: 1(-0.95,0.95) 2(-0.95,-0.95) 3(0.95,0)
  silkscreen extent 0.2,-1.5 0.7,1.5, body extent -1.16,-1.45 1.21,1.45, height 1
SOT-23#2 [mm] "SOT23, 3-Leads, Body 2.9x1.3mm, Pitch 0.95mm, Lead Span 2.5mm, IPC Medium Density"
  rrect50% 1x0.6 smd: 1(-1.2,0.95) 2(-1.2,-0.95) 3(1.2,0)
  silkscreen extent -1.62,-1.5 0.7,1.5, body extent -1.16,-1.45 1.21,1.45, height 1
SOT-363 [mm]
  rect 0.6x0.42 smd mask+0.051: 1(-0.95,0.65) 2(-0.95,0) 3(-0.95,-0.65) 4(0.95,-0.65) 5(0.95,0) 6(0.95,0.65)
  silkscreen extent -0.38,-1.02 0.38,1.02, body extent -1.1,-1.1 1.1,1.1, height 1.12
SW_NK236W [mm] "APEM"
  rect 1.7x1.7 hole 1: 1(0,0)
  round 1.7 hole 1: 2(-2.54,0) 3(2.54,0)
  silkscreen extent -5,-7.2 5,-0.7, body extent -5,-7.15 5,0.35, height 2.57
TO-220-2 [mm] "CREE"
  rect 1.9x1.9 hole 1.4: 1(-2.54,0)
  round 1.9 hole 1.4: 2(2.54,0)
  silkscreen extent -5.25,-1.64 5.26,3.01, body extent -5.21,-1.57 5.21,3.12, height 19.47
TO-220AB#1 [mil] "Copied from Altium's version of TO3B"
  rect 60x118.11 hole 50: 1(-100,0)
  oval 60x118.11 hole 50: 2(0,0) 3(100,0)
  silkscreen extent -225,-73 225,130, body extent -221,-59 221,126, height 765
TO-220AB#2 [mil] "Copied from Altium's version of TO3B"
  rect 76x118.11 hole 50: 1(-100,0)
  oval 76x118.11 hole 50: 2(0,0) 3(100,0)
  silkscreen extent -225,-73 225,130, body extent -221,-59 221,126, height 765
TRANS_NexFET_Q5B#1 [mm] "TI recommended land pattern (nominal) November 2012"
  rect 1.372x0.71 smd paste-0.4: 1(-2.776,1.905) 2(-2.776,0.635) 3(-2.776,-0.635) 4(-2.776,-1.905)
  rect 0.59x0.71 smd paste-0.3: 5(2.776,-1.905) 6(2.776,-0.635) 7(2.776,0.635) 8(2.776,1.905)
  Top Layer region: -1.106,-2.26 2.744,-2.26 2.744,2.26 -1.106,2.26
  silkscreen extent -3.38,-2.7 3,2.7, body extent -3.23,-2.55 2.87,2.55, height 1.06
TRANS_NexFET_Q5B#2 [mm] "TI recommended land pattern (nominal) November 2012"
  rect 1.372x0.71 smd paste-0.4 mask+0.051: 1(-2.776,1.905) 2(-2.776,0.635) 3(-2.776,-0.635) 4(-2.776,-1.905)
  rect 0.59x0.71 smd paste-0.3: 5(2.776,-1.905) 6(2.776,-0.635) 7(2.776,0.635) 8(2.776,1.905)
  Top Layer region: -1.106,-2.26 2.744,-2.26 2.744,2.26 -1.106,2.26
  body extent -3.23,-2.55 2.87,2.55, height 1.06
WE-DD_7332 [mm] "Wurth"
  rect 1x2.2 smd: 1(-0.9,2.65) 2(-0.9,-2.65) 3(0.9,-2.65) 4(0.9,2.65)
  silkscreen extent -3.5,-3.5 3.5,3.5, body extent -3.65,-3.65 3.65,3.65, height 4.02
WE-HCA2 [mm] "Wurth Electronik recommended land pattern"
  rect 4.5x5 smd: 1(-5.25,0) 2(5.25,0)
  silkscreen extent -7.35,-6.85 7.35,6.85, body extent -7.01,-6.65 7.01,6.67, height 5
XFMR_CS4200V-01L [mil] "COILCRAFT"
  rect 100x100 hole 70: 1(-200,300)
  round 120 hole 89: 2(-200,-300) 3(200,-300)
  round 100 hole 70: 4(200,300)
  silkscreen extent -290,-390 290,390, body extent -285,-385 285,385, height 781
XFMR_PQ20-149 [mil] "CLiCK"
  round 70 hole 36: 2(-397.64,248.03) 3(-397.64,98.43) 4(-397.64,-98.43) 5(-397.64,-248.03) 8(397.64,-299.21) 9(397.64,-200.79) 10(397.64,-102.36) 11(397.64,94.49) 12(397.64,192.91)
  silkscreen extent -508,-488 508,488, body extent -497,-479 496,482, height 1004
XFMR_VITEC-492x472x452 [mm] "Vitec, Gate Drive Transformer"
  rect 1.778x1.778 hole 1: 1(-3.75,3.75)
  round 1.778 hole 1: 2(-3.75,1.25) 3(-3.75,-1.25) 4(-3.75,-3.75) 5(3.75,-3.75) 6(3.75,-1.25) 7(3.75,1.25) 8(3.75,3.75)
  silkscreen extent -5.25,-6.25 5.25,6.25, body extent -5.25,-6.25 5.25,6.25, height 12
